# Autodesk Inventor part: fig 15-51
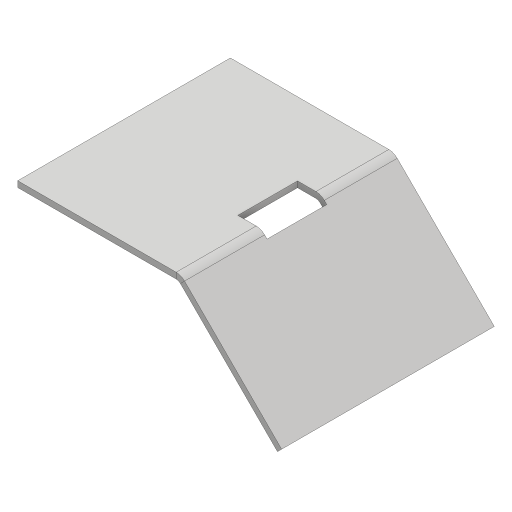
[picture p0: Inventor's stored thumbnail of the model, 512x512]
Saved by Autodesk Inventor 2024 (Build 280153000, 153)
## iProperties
Created: 2015-07
Part Number: fig 15-51
Material: Generic
Document SubType Name: Sheet Metal
Designer: Sandeep
Density: 1 g/cm^3
Sheet Metal Rule: Default_mm
Appearance: Default
Author: Sandeep
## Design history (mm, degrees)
node "Face1"
  sketch "Sketch1"
    geometry: L1 (-9.283, 8.313)-(4.503, 8.313); L2 (4.503, 8.313)-(4.503, -9.63); L3 (4.503, -9.63)-(-9.283, -9.63); L4 (-9.283, -9.63)-(-9.283, 8.313); 1 further point
    constraints: 8 end point, 2 parallel, 1 horizontal, 1 perpendicular
node "Flange1"
sketch "Sketch3"
  geometry: L1 (2.535, 2.162)-(6.789, 2.162); L2 (6.789, 2.162)-(6.789, -2.878); L3 (6.789, -2.878)-(2.535, -2.878); L4 (2.535, -2.878)-(2.535, 2.162); 1 further point
  constraints: 8 end point, 2 parallel, 1 horizontal, 1 perpendicular
cut "Cut1" sketch "Sketch3" dims "d11" = 0.5 (= Thickness), "d12" = 0
body "Solid1"
face "Plate1" dims "d13" = 0.5 (= Thickness)
sketch "Sketch2"
  geometry: L1 (0, -12)-(17.943, -12); L2 (17.943, -12)-(17.943, 0); 1 other entity
  constraints: 4 end point, 4 other
face "Plate2" dims "d1" = 0.5 (= BendReliefWidth), "d2" = 0.25 (= BendReliefDepth), "d3" = 1 (= MinimumRemnant), "d4" = 0.5 (= BendRadius), "d5" = 12, "d6" = 45 deg, "d7" = 0.5 (= BendRadius), "d8" = 2 (= CornerReliefSize), "d9" = 0.5 (= GapSize), "d10" = 0.5 (= JacobiRadiusSize), "d13" = 0.5 (= Thickness), "SeamGap" = 0.01
bend "Bend1" dims "d1" = 0.5 (= BendReliefWidth), "d2" = 0.25 (= BendReliefDepth), "d3" = 1 (= MinimumRemnant), "d4" = 0.5 (= BendRadius), "d5" = 12, "d6" = 45 deg, "d7" = 0.5 (= BendRadius), "d13" = 0.5 (= Thickness), "SeamGap" = 0.01
feature "Corner1" dims "d5" = 12, "d6" = 45 deg, "d8" = 2 (= CornerReliefSize), "d9" = 0.5 (= GapSize), "d10" = 0.5 (= JacobiRadiusSize)
other parameters: "Thickness" = 0.5, "BendRadius" = 0.5 (= Thickness), "BendReliefWidth" = 0.5 (= Thickness), "BendReliefDepth" = 0.25 (= 0.5 x Thickness), "CornerReliefSize" = 2 (= 4 x Thickness), "MinimumRemnant" = 1 (= 2 x Thickness), "TransitionRadius" = 0.5 (= BendRadius), "JacobiRadiusSize" = 0.5 (= BendRadius), "GapSize" = 0.5 (= Thickness), "d0" = 0.5 (= BendRadius)
